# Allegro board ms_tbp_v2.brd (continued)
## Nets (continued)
SAS_B2_TX4P: J23.G3 J24.1C7
SAS_B2_TX5N: J23.F4 J24.2D5
SAS_B2_TX5P: J23.E4 J24.2D4
SAS_B2_TX6N: J23.B5 J24.2C5
SAS_B2_TX6P: J23.A5 J24.2C4
SAS_B2_TX7N: J23.H5 J24.2D8
SAS_B2_TX7P: J23.G5 J24.2D7
SAS_B2_TX8N: J23.F6 J24.2C8
SAS_B2_TX8P: J23.E6 J24.2C7
SERIAL_B1_RX1: J7.G3 J11.B3 U1.S2
SERIAL_B1_RX2: J1.I8 J7.G4 U1.S6
SERIAL_B1_TX1: J7.H3 J11.A3 U1.S1
SERIAL_B1_TX2: J1.H8 J7.H4 U1.S5
SERIAL_B2_RX1: J19.G3 J23.B3 U1.S11
SERIAL_B2_RX2: J13.I8 J19.G4 U1.S7
SERIAL_B2_TX1: J19.H3 J23.A3 U1.S12
SERIAL_B2_TX2: J13.H8 J19.H4 U1.S8
SKU_B1_ID0: J7.F3 R2.2(B<0>) R3.1(A<0>)
SKU_B1_ID1: J7.I4 R4.2(B<0>) R5.1(A<0>)
SKU_B1_ID2: J7.F2 R6.2(B<0>) R7.1(A<0>) R75.1(A<0>)
SKU_B2_ID0: J19.F3 R30.2(B<0>) R31.1(A<0>)
SKU_B2_ID1: J19.I4 R32.2(B<0>) R33.1(A<0>)
SKU_B2_ID2: J19.F2 R34.2(B<0>) R35.1(A<0>) R61.1(A<0>)
UNNAMED_4_1X2HDR_I81_IO: J25.2(IO<2>) R9.1(A<0>)
UNNAMED_4_1X2HDR_I90_IO: J26.2(IO<2>) R11.1(A<0>)
UNNAMED_4_FERRITE_I148_A: FB1.1(A) FS1.2(B<0>)
UNNAMED_4_FERRITE_I151_B: FB2.2(B) FS2.1(A<0>)
UNNAMED_6_1X2HDR_I52_IO: J28.2(IO<2>) R37.1(A<0>)
UNNAMED_6_1X2HDR_I56_IO: J29.2(IO<2>) R39.1(A<0>)
UNNAMED_6_FERRITE_I24_A: FB3.1(A) FS3.2(B<0>)
UNNAMED_6_FERRITE_I27_B: FB4.2(B) FS4.1(A<0>)
UNNAMED_8_FERRITE_I47_B: FB7.2(B) FS7.1(A<0>)
UNNAMED_8_FERRITE_I51_A: FB5.1(A) FS5.2(B<0>)
UNNAMED_8_FERRITE_I54_A: FB6.1(A) FS6.2(B<0>)
UNNAMED_16_FERRITE_I40_A: FB9.1(A) FS9.2(B<0>)
UNNAMED_16_FERRITE_I46_B: FB10.2(B) FS10.1(A<0>)
UNNAMED_16_FERRITE_I115_A: FB8.1(A) FS8.2(B<0>)
USB_B1_N: J1.C10 U2.2(IO<2>)
USB_B1_P: J1.B10 U2.3(IO<3>)
USB_B2_N: J13.C10 U3.2(IO<2>)
USB_B2_P: J13.B10 U3.3(IO<3>)

Pads without a net: J1 G7; J7 E2; J12 1A1 1A2 1B1 1B2 1C1 1C2 1D1 1D2 2A1 2A2 2B1 2B2 2C1 2C2 2D1 2D2; J13 G7; J19 E2; J24 1A1 1A2 1B1 1B2 1C1 1C2 1D1 1D2 2A1 2A2 2B1 2B2 2C1 2C2 2D1 2D2

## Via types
v1: diameter 0.559, hole 0.254, TOP to BOTTOM, 1600 vias

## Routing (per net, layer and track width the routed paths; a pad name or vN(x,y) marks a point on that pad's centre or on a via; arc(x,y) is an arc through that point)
GND: length 293.7
  TOP w0.305: J14.135 v1(270.92,27.93) ; J8.20 v1(99.21,4.79) ; v1(359.71,15.27) J17.14 v1(359.71,12.39) ; J2.79 v1(49.92,19.04) ; J2.118 v1(48.65,25.39) ; J2.22 v1(48.65,10.15) ; R11.2 77.91,43.55 v1(77.86,43.5) ; C8.2 v1(136.74,5.51) ; C7.2 v1(136.74,6.65) ; J14.120 v1(272.19,25.39) ; J2.58 v1(43.57,16.5) ; J14.58 v1(264.57,16.5) ; J2.147 v1(44.84,30.47) ; J2.126 v1(48.65,26.66) ; J14.141 v1(268.38,29.2) ; J14.105 v1(263.21,23.49) ; J2.11 v1(44.84,8.88) ; R12.2 v1(122.99,39.71) ; J2.77 v1(47.38,19.04) ; J20.38 v1(334.61,4.79) ; C12.2 v1(357.74,5.51) ; J2.13 v1(47.38,8.88) ; v1(43.58,11.43) 43.57,11.43 43.57,11.42 J2.26 ; v1(263.21,22.22) 263.43,22.22 263.45,22.19 263.89,22.19 263.92,22.22 J14.97 ; J2.141 v1(47.38,29.2) ; J14.124 v1(267.11,26.66) ; J20.23 v1(322.61,4.79) ; v1(138.71,12.39) J5.14 v1(138.71,15.27) ; J8.4 110.81,10.06 v1(110.81,10.03) ; J2.56 v1(51.19,15.23) ; J14.35 v1(265.84,12.69) ; J14.101 v1(268.38,22.85) ; R23.2 v1(124.9,44.48) ; v1(85.95,29.14) 85.97,29.16 C4.2 ; C1.2 88.95,29.48 v1(88.95,29.47) ; J14.56 v1(272.19,15.23) ; v1(357.31,15.27) J17.11 v1(357.31,12.41) ; J2.135 v1(49.92,27.93) ; v1(42.21,22.22) 42.43,22.22 42.45,22.19 42.89,22.19 42.92,22.22 J2.97 ; J14.65 262.95,17.14 v1(262.77,16.95) ; J2.107 v1(44.84,24.12) ; J2.32 v1(51.19,11.42) ; v1(263.23,14.11) 263.94,13.4 J14.41 ; v1(310.19,42.51) 310.2,42.51 R63.2 ; J14.52 v1(267.11,15.23) ; J14.88 v1(272.19,20.31) ; J20.1 334.21,10.06 v1(334.21,10.03) ; J2.129 v1(42.21,27.3) ; J14.24 v1(272.19,10.15) ; J2.146 v1(43.57,30.47) ; v1(403.43,6.44) 403.41,6.45 R71.1 ; C5.2 v1(144.01,6.65) ; J2.96 v1(51.19,21.58) ; R86.1 258.95,18.16 v1(258.96,18.15) ; J2.62 v1(48.65,16.5) ; J14.9 v1(263.21,8.25) ; J2.65 v1(42.21,17.14) ; J14.147 v1(265.84,30.47) ; v1(356.74,23.54) 356.91,23.37 J17.10 ; v1(263.15,11.57) 263.64,12.05 J14.33 ; J5.1 143.11,23.34 v1(143.31,23.54) ; R39.2 v1(298.91,43.36) ; J14.67 v1(265.84,17.77) ; J2.64 v1(51.19,16.5) ; J14.3 v1(265.84,7.61) ; J2.35 v1(44.84,12.69) ; J20.26 v1(325.01,4.79) ; J2.124 v1(46.11,26.66) ; C3.2 v1(70.09,16.17) ; v1(136.31,12.41) J5.11 v1(136.31,15.27) ; J2.101 v1(47.38,22.85) ; J14.107 v1(265.84,24.12) ; v1(362.11,12.39) J17.17 v1(362.11,15.27) ; J2.88 v1(51.19,20.31) ; J2.71 v1(49.92,17.77) ; J2.75 v1(44.84,19.04) ; R79.2 v1(92.56,42.33) ; J8.1 113.21,10.06 v1(113.21,10.03) ; J14.114 v1(264.57,25.39) ; J14.126 v1(269.65,26.66) ; J2.92 v1(46.11,21.58) ; v1(143.51,12.39) J5.20 v1(143.51,15.27) ; v1(364.51,12.39) J17.20 v1(364.51,15.27) ; J2.41 v1(42.21,13.33) ; J14.1 v1(263.21,6.98) ; J14.122 v1(264.57,26.66) ; J14.54 v1(269.65,15.23) ; J20.7 329.41,10.06 v1(329.41,10.03) ; v1(144.03,5.51) C6.2 ; v1(309.57,29.5) 309.57,29.5 C13.2 ; J20.16 322.21,10.06 v1(322.21,10.03) ; R25.2 v1(119.95,45.36) ; v1(141.11,15.27) J5.17 v1(141.11,12.39) ; J14.39 v1(270.92,12.69) ; J14.84 v1(267.11,20.31) ; J14.22 v1(269.65,10.15) ; J20.13 324.61,10.06 v1(324.61,10.03) ; J2.24 v1(51.19,10.15) ; J2.114 v1(43.57,25.39) ; J14.43 v1(265.84,13.96) ; J2.37 v1(47.38,12.69) ; J14.28 v1(267.11,11.42) ; J14.103 v1(270.92,22.85) ; v1(364.31,23.54) 364.11,23.34 J17.1 ; J2.82 v1(43.57,20.31) ; J2.94 v1(48.65,21.58) ; J2.28 v1(46.11,11.42) ; R21.2 v1(124.77,47.27) ; J14.92 v1(267.11,21.58) ; J8.35 v1(111.21,4.79) ; R37.2 v1(307.04,43.15) ; J14.30 v1(269.65,11.42) ; J14.11 v1(265.84,8.88) ; v1(319.81,10.03) 319.81,10.06 J20.19 ; J2.45 v1(47.38,13.96) ; J2.90 v1(43.57,21.58) ; J8.32 v1(108.81,4.79) ; J2.9 v1(42.21,8.25) ; J14.5 v1(268.38,7.61) ; J20.4 331.81,10.06 v1(331.81,10.03) ; J2.111 v1(49.92,24.12) ; v1(89.57,38.14) 89.57,38.14 R77.2 ; C11.2 v1(357.74,6.65) ; J14.133 v1(268.38,27.93) ; J2.60 v1(46.11,16.5) ; J8.19 98.81,10.06 v1(98.81,10.03) ; J14.20 v1(267.11,10.15) ; J14.86 v1(269.65,20.31) ; R9.2 v1(86.04,43.15) ; J14.32 v1(272.19,11.42) ; J2.116 v1(46.11,25.39) ; J14.73 v1(264.57,19.04) ; J8.23 v1(101.61,4.79) ; J2.7 v1(49.92,7.61) ; J2.39 v1(49.92,12.69) ; J14.146 v1(264.57,30.47) ; J14.109 v1(268.38,24.12) ; J14.18 v1(264.57,10.15) ; J2.3 v1(44.84,7.61) ; J2.47 v1(49.92,13.96) ; J14.82 v1(264.57,20.31) ; J14.26 264.57,11.42 264.57,11.43 v1(264.58,11.43) ; J2.122 v1(43.57,26.66) ; J2.20 v1(46.11,10.15) ; J2.99 v1(44.84,22.85) ; J2.133 v1(47.38,27.93) ; J14.45 v1(268.38,13.96) ; J8.38 v1(113.61,4.79) ; J14.13 v1(268.38,8.88) ; J2.15 v1(49.92,8.88) ; J5.10 135.91,23.37 v1(135.74,23.54) ; J20.32 v1(329.81,4.79) ; J2.86 v1(48.65,20.31) ; J8.13 103.61,10.06 v1(103.61,10.03) ; J2.67 v1(44.84,17.77) ; J2.18 v1(43.57,10.15) ; J14.139 v1(265.84,29.2) ; J2.50 v1(43.57,15.23) ; J8.16 101.21,10.06 v1(101.21,10.03) ; J14.62 v1(269.65,16.5) ; J14.75 v1(265.84,19.04) ; J14.37 v1(268.38,12.69) ; J2.52 v1(46.11,15.23) ; J2.131 v1(44.84,27.93) ; J2.1 v1(42.21,6.98) ; J14.69 v1(268.38,17.77) ; J14.118 v1(269.65,25.39) ; C15.2 306.59,29.18 v1(306.58,29.17) ; J14.116 v1(267.11,25.39) ; J14.131 v1(265.84,27.93) ; J2.54 v1(48.65,15.23) ; J14.90 v1(264.57,21.58) ; J14.129 v1(263.21,27.3) ; J14.94 v1(269.65,21.58) ; J14.111 v1(270.92,24.12) ; J2.73 v1(42.21,18.41) ; J8.26 v1(104.01,4.79) ; J2.30 v1(48.65,11.42) ; R5.2 120.05,41.14 v1(119.82,41.36) ; R3.2 v1(127.82,40.22) ; J2.139 v1(44.84,29.2) ; J14.99 v1(265.84,22.85) ; J2.103 v1(49.92,22.85) ; J14.79 v1(270.92,19.04) ; J2.105 v1(42.21,23.49) ; J8.7 108.41,10.06 v1(108.41,10.03) ; R85.1 v1(35.27,18.16) ; J2.84 v1(46.11,20.31) ; J2.69 v1(47.38,17.77) ; J14.71 v1(270.92,17.77) ; J2.120 v1(51.19,25.39) ; J14.96 v1(272.19,21.58) ; J14.60 v1(267.11,16.5) ; J14.64 v1(272.19,16.5) ; J14.50 v1(264.57,15.23) ; J14.128 v1(272.19,26.66) ; C9.2 v1(365.01,6.65) ; v1(365.03,5.51) C10.2 ; C2.2 v1(66.83,16.59) ; J20.35 v1(332.21,4.79) ; J14.47 v1(270.92,13.96) ; J2.128 v1(51.19,26.66) ; J14.77 v1(268.38,19.04) ; J14.7 v1(270.92,7.61) ; J2.5 v1(47.38,7.61) ; J14.15 v1(270.92,8.88) ; J2.33 v1(42.21,12.05) ; J20.20 v1(320.21,4.79) ; J2.109 v1(47.38,24.12) ; J2.43 v1(44.84,13.96)
  TOP w0.381: 216.52,25.69 J27.4 ; J27.4 218.52,25.69 ; J27.4 218.52,23.7 ; J27.4 216.52,23.7 ; 220.08,14.12 U3.4 ; U3.4 221.63,14.12 ; U3.4 221.63,15.66 ; U3.4 220.08,15.66 ; J27.2 224.02,25.69 ; J27.2 224.02,23.7 ; J27.2 222.02,25.69 ; J27.2 222.02,23.7
  LYR2 w0.381: 216.52,25.69 J27.4 ; J27.4 218.52,23.7 ; J27.4 218.52,25.69 ; J27.4 216.52,23.7 ; J27.2 224.02,23.7 ; J27.2 222.02,23.7 ; J27.2 222.02,25.69 ; J27.2 224.02,25.69 ; 2.84,25.91 U2.4 ; U2.4 2.84,24.37 ; U2.4 4.39,24.37 ; U2.4 4.39,25.91 ; 220.08,14.12 U3.4 ; U3.4 221.63,15.66 ; U3.4 220.08,15.66 ; U3.4 221.63,14.12
  LYR3 w0.381: 222.02,25.69 J27.2 ; J27.2 224.02,25.69 ; J27.2 224.02,23.7 ; J27.2 222.02,23.7 ; J27.4 218.52,25.69 ; J27.4 218.52,23.7 ; J27.4 216.52,25.69 ; J27.4 216.52,23.7 ; 220.08,14.12 U3.4 ; U3.4 220.08,15.66 ; U3.4 221.63,15.66 ; U3.4 221.63,14.12
  LYR5 w0.381: 2.84,25.91 U2.4 ; U2.4 2.84,24.37 ; U2.4 4.39,24.37 ; U2.4 4.39,25.91
  LYR7 w0.381: J27.2 224.02,23.7 ; J27.2 224.02,25.69 ; J27.2 222.02,23.7 ; J27.2 222.02,25.69 ; U3.4 221.63,15.66 ; U3.4 220.08,14.12 ; U3.4 220.08,15.66 ; U3.4 221.63,14.12 ; 216.52,25.69 J27.4 ; J27.4 218.52,23.7 ; J27.4 218.52,25.69 ; J27.4 216.52,23.7 ; 2.84,25.91 U2.4 ; U2.4 4.39,24.37 ; U2.4 2.84,24.37 ; U2.4 4.39,25.91
  vias: v1(1.2,42.13) v1(1.84,15.71) v1(7.68,15.58) v1(32.55,46.91) v1(32.55,45.64) v1(32.55,44.37) v1(33.82,46.91) v1(33.82,45.64) v1(33.82,44.37) v1(35.09,46.91) v1(35.09,45.64) v1(35.09,44.37) v1(36.36,46.91) v1(36.36,45.64) v1(36.36,44.37) v1(37.63,46.91) v1(37.63,45.64) v1(37.63,44.37) v1(38.9,46.91) v1(38.9,45.64) v1(38.9,44.37) v1(40.17,46.91) v1(40.17,45.64) v1(40.17,44.37) v1(41.44,46.91) v1(41.44,45.64) v1(41.44,44.37) v1(42.71,46.91) v1(42.71,45.64) v1(42.71,44.37) v1(43.98,46.91) v1(43.98,45.64) v1(43.98,44.37) v1(45.25,46.91) v1(45.25,45.64) v1(45.25,44.37) v1(46.52,46.91) v1(46.52,45.64) v1(46.52,44.37) v1(47.79,46.91) v1(47.79,45.64) v1(47.79,44.37) v1(49.06,46.91) v1(49.06,45.64) v1(49.06,44.37) v1(50.33,46.91) v1(50.33,45.64) v1(50.33,44.37) v1(54.16,27.77) v1(54.16,21.42) v1(54.16,15.07) v1(54.16,8.72) v1(57.34,24.6) v1(57.34,5.55) v1(57.59,27.77) v1(57.97,50.25) v1(58.86,29.43) v1(59.11,26.25) v1(59.24,30.85) v1(60.51,8.72) v1(61.46,29.36) v1(61.78,53.68) v1(61.91,45.43) v1(62.16,26.25) v1(63.69,34.12) v1(63.69,5.55) v1(63.81,24.47) v1(65.27,29.04) v1(65.27,23.01) v1(66.73,25.49) v1(66.86,30.95) v1(66.86,21.42) v1(66.86,8.72) v1(68,53.57) v1(68.13,49.87) v1(68.13,23.01) v1(68.26,45.43) v1(68.45,29.04) v1(70.04,34.12) v1(70.04,18.25) v1(70.04,11.9) v1(70.04,5.55) v1(71.31,51.78) v1(71.31,47.97) v1(71.62,29.04) v1(71.94,23.01) v1(73.21,30.95) v1(73.51,36.56) v1(74.16,21.42) v1(74.48,53.68) v1(74.48,49.87) v1(74.8,29.04) v1(76.07,23.01) v1(76.39,34.12) v1(77.66,51.78) v1(77.66,47.97) v1(77.97,29.04) v1(79.41,30.95) v1(80.83,53.68) v1(80.83,49.87) v1(81.29,28.99) v1(82.74,34.12) v1(84.01,51.78) v1(84.01,43.01) v1(84.54,30.98) v1(87.18,53.68) v1(87.18,49.87) v1(90.36,51.78) v1(93.53,53.68) v1(99.02,12.03) v1(99.02,10.86) v1(99.42,3.94) v1(99.42,2.77) v1(99.88,53.68) v1(101,12.03) v1(101,10.86) v1(101.39,13.94) v1(101.34,4.01) v1(101.4,2.77) v1(101.42,12.73) v1(103.06,35.39) v1(103.4,13.9) v1(103.4,12.73) v1(105.47,3.16) v1(105.47,1.18) v1(106.23,53.68) v1(106.23,44.92) v1(106.23,38.57) v1(106.23,32.22) v1(106.63,3.16) v1(106.63,1.18) v1(108.05,3.5) v1(108.05,2.33) v1(108.62,16.46) v1(108.62,15.29) v1(109.41,38.57) v1(109.41,35.39) v1(110.03,3.5) v1(110.03,2.33) v1(110.6,16.46) v1(110.6,15.29) v1(111.03,12.51) v1(111.03,11.34) v1(112.58,53.68) v1(113.01,12.51) v1(113.01,11.34) v1(114.68,8.07) v1(114.68,6.91) v1(116.66,8.07) v1(116.66,6.91) v1(117.79,51.37) v1(118.93,53.68) v1(125.28,53.68) v1(131.63,53.68) v1(133.54,49.36) v1(136.46,46.19) v1(136.52,11.17) v1(136.52,10) v1(136.76,17.23) v1(137.88,17.23) v1(137.98,53.68) v1(138.5,11.17) v1(138.5,10) v1(140.14,49.36) v1(140.27,20.5) v1(140.27,18.51) v1(141.43,20.5) v1(141.43,18.51) v1(143.06,46.19) v1(144.33,53.68) v1(160.21,53.68) v1(164.46,24.46) v1(164.6,31.18) v1(165.19,39.52) v1(165.29,48.09) v1(165.25,35.76) v1(165.25,32) v1(165.25,28.18) v1(166.25,30.7) v1(166.32,26.78) v1(166.56,53.68) v1(167.5,35.76) v1(167.6,27.91) v1(168.5,34.54) v1(168.5,30.73) v1(168.47,26.96) v1(169.31,30.83) v1(169.91,39.61) v1(172.78,48.09) v1(172.91,53.68) v1(175.63,31.25) v1(176.25,28.18) v1(176.25,24.38) v1(177.25,38.34) v1(177.25,30.73) v1(177.22,26.96) v1(178.55,24.33) v1(179.18,35.34) v1(179.26,53.68) v1(179.26,48.09) v1(179.5,38.34) v1(179.5,34.54) v1(179.5,30.73) v1(179.47,26.96) v1(180.33,30.86) v1(185.61,53.68) v1(185.61,48.09) v1(188.15,51.27) v1(188.15,44.92) v1(188.15,38.57) v1(188.15,32.22) v1(188.15,25.87) v1(188.15,19.52) v1(188.15,6.82) v1(191.32,48.09) v1(191.32,35.39) v1(191.32,29.04) v1(191.32,22.69) v1(191.32,16.34) v1(191.32,9.49) v1(191.45,53.68) v1(194.5,51.27) v1(194.5,44.92) v1(194.5,38.57) v1(194.5,32.22) v1(194.5,25.87) v1(194.5,6.82) v1(197.67,53.68) v1(197.67,48.09) v1(197.67,35.39) v1(197.67,29.04) v1(197.67,22.69) v1(197.67,16.34) v1(197.67,9.49) v1(200.85,51.27) v1(200.85,44.92) v1(200.85,38.57) v1(200.85,32.22) v1(200.85,25.87) v1(200.85,6.82) v1(204.02,53.68) v1(204.02,48.09) v1(204.02,35.39) v1(204.02,29.04) v1(204.02,22.69) v1(204.02,16.34) v1(204.02,9.49) v1(207.2,51.27) v1(207.2,44.92) v1(207.2,38.57) v1(207.2,32.22) v1(207.2,25.87) v1(207.2,6.82) v1(210.24,53.68) v1(210.37,35.39) v1(210.37,29.04) v1(210.37,22.69) v1(210.37,16.34) v1(210.37,9.49) v1(213.55,51.27) v1(213.55,44.92) v1(213.55,38.57) v1(213.55,32.22) v1(213.55,25.87) v1(213.55,19.52) v1(213.55,13.17) v1(213.55,6.82) v1(216.72,53.68) v1(216.72,48.09) v1(216.72,38.57) v1(216.72,35.39) v1(216.72,32.22) v1(216.72,19.52) v1(216.72,16.34) v1(216.72,13.17) v1(216.72,9.99) v1(216.72,6.82) v1(219.9,51.27) v1(219.9,44.92) v1(219.9,38.57) v1(219.9,35.39) v1(219.9,32.22) v1(219.9,19.52) v1(222.94,19.52) v1(223.07,53.68) v1(223.07,48.09) v1(223.07,38.57) v1(223.07,35.39) v1(223.07,32.22) v1(226.25,51.27) v1(226.25,44.92) v1(226.25,38.57) v1(226.25,32.22) v1(226.25,25.87) v1(226.25,19.52) v1(226.25,13.17) v1(226.25,6.82) v1(229.42,53.68) v1(229.42,48.09) v1(229.42,35.39) v1(229.42,29.04) v1(229.42,22.69) v1(229.42,16.34) v1(232.6,51.27) v1(232.6,44.92) v1(232.6,38.57) v1(235.77,53.68) v1(235.77,48.09) v1(235.77,35.39) v1(238.95,51.27) v1(238.95,44.92) v1(238.95,38.57) v1(242.12,53.68) v1(242.12,48.09) v1(245.3,51.27) v1(245.3,44.92) v1(245.3,38.57) v1(248.47,53.68) v1(248.47,48.09) v1(251.65,51.27) v1(251.65,44.92) v1(251.65,38.57) v1(254.82,53.68) v1(255.96,49.87) v1(255.96,46.82) v1(255.96,40.47) v1(261.81,53.68) v1(262.44,46.82) v1(262.44,43.52) v1(266,53.68) v1(266,46.82) v1(266,40.47) v1(269.43,53.17) v1(269.43,46.82) v1(269.43,40.47) v1(272.6,50) v1(272.6,43.65) v1(275.78,53.17) v1(275.78,46.82) v1(275.78,40.47) v1(275.78,17.61) v1(275.78,11.26) v1(275.78,4.91) v1(278.95,50) v1(278.95,43.65) v1(278.95,33.49) v1(278.95,14.44) v1(278.95,8.09) v1(282.13,53.17) v1(282.13,46.82) v1(282.13,40.47) v1(282.13,11.26) v1(282.13,4.91) v1(285.3,50) v1(285.3,43.65) v1(285.3,33.49) v1(285.3,27.14) v1(285.3,20.79) v1(285.3,14.44) v1(285.3,8.09) v1(288.48,53.17) v1(288.48,46.82) v1(288.48,40.47) v1(288.48,30.31) v1(288.48,23.96) v1(288.48,17.61) v1(288.48,11.26) v1(288.48,4.91) v1(291.65,50) v1(291.65,43.65) v1(291.65,33.49) v1(291.65,27.14) v1(291.65,20.79) v1(291.65,14.44) v1(291.65,8.09) v1(294.83,53.17) v1(294.83,46.82) v1(294.83,40.47) v1(294.83,30.31) v1(294.83,23.96) v1(298,50) v1(298,27.14) v1(301.18,53.17) v1(301.18,40.47) v1(304.35,43.65) v1(305.25,51.67) v1(307.53,53.17) v1(309.7,51.67) v1(313.88,53.17) v1(317.43,53.17) v1(320.02,12.03) v1(320.02,10.86) v1(320.23,53.17) v1(320.42,3.94) v1(320.42,2.77) v1(322,12.03) v1(322,10.86) v1(322.39,13.94) v1(322.34,4.01) v1(322.4,2.77) v1(322.42,12.73) v1(323.4,53.17) v1(324.29,48.6) v1(324.29,45.17) v1(324.29,42) v1(324.29,38.82) v1(324.29,35.65) v1(324.4,13.9) v1(324.4,12.73) v1(326.47,3.16) v1(326.47,1.18) v1(326.58,53.17) v1(327.46,45.17) v1(327.46,42) v1(327.46,38.82) v1(327.46,35.65) v1(327.63,3.16) v1(327.63,1.18) v1(329.05,3.5) v1(329.05,2.33) v1(329.62,16.46) v1(329.62,15.29) v1(329.75,53.17) v1(330.64,45.17) v1(330.64,42) v1(330.64,38.82) v1(330.64,35.65) v1(330.89,27.88) v1(331.03,3.5) v1(331.03,2.33) v1(331.6,16.46) v1(331.6,15.29) v1(332.03,12.51) v1(332.03,11.34) v1(332.62,27.75) v1(332.93,53.17) v1(334.07,45.17) v1(334.07,42) v1(334.07,38.82) v1(334.07,35.52) v1(334.11,27.89) v1(334.01,12.51) v1(334.01,11.34) v1(335.49,27.77) v1(335.68,8.07) v1(335.68,6.91) v1(336.1,53.17) v1(337.12,46.06) v1(337.12,42.89) v1(337.12,36.54) v1(337.66,8.07) v1(337.66,6.91) v1(339.28,53.17) v1(340.29,33.36) v1(342.45,53.17) v1(345.63,53.17) v1(348.8,53.17) v1(350.07,23.81) v1(350.07,22.72) v1(351.98,53.17) v1(354.39,49.87) v1(354.39,46.7) v1(355.15,53.17) v1(357.56,49.87) v1(357.56,46.7) v1(357.56,43.52) v1(357.52,11.17) v1(357.52,10) v1(357.76,17.23) v1(358.33,53.17) v1(358.88,17.23) v1(359.5,11.17) v1(359.5,10) v1(360.74,49.87) v1(360.74,46.7) v1(360.74,43.52) v1(360.74,39.71) v1(361.27,20.5) v1(361.27,18.51) v1(361.5,53.17) v1(362.43,20.5) v1(362.43,18.51) v1(363.91,49.87) v1(364.04,46.57) v1(364.68,53.17) v1(367.85,53.17) v1(371.03,53.17) v1(374.1,53.24) v1(377.38,53.17) v1(380.55,53.17) v1(383.73,53.17) v1(385.46,24.46) v1(385.6,31.18) v1(386.25,35.76) v1(386.25,32) v1(386.25,28.18) v1(386.36,39.51) v1(386.9,53.17) v1(387.15,47.84) v1(387.15,44.67) v1(387.25,30.7) v1(387.3,26.79) v1(388.5,35.76) v1(388.6,27.91) v1(389.5,34.54) v1(389.5,30.7) v1(389.47,26.96) v1(390.08,53.17) v1(390.3,30.85) v1(390.33,47.84) v1(390.33,44.67) v1(390.81,39.46) v1(393.25,53.17) v1(393.5,47.84) v1(393.5,44.67) v1(393.5,41.49) v1(396.43,53.17) v1(396.68,47.84) v1(396.68,44.67) v1(396.68,41.49) v1(396.63,31.25) v1(397.25,28.18) v1(397.25,24.38) v1(398.25,38.34) v1(398.25,30.73) v1(398.22,26.96) v1(399.6,53.17) v1(399.55,24.33) v1(399.85,47.84) v1(399.85,44.67) v1(400.18,35.34) v1(400.5,38.34) v1(400.5,34.54) v1(400.5,30.73) v1(400.47,26.96) v1(401.3,30.86) v1(402.78,53.17) v1(403.03,47.84) v1(403.03,44.67) v1(403.03,41.49) v1(404.25,19.27) v1(404.3,16.09) v1(404.3,12.92) v1(404.3,9.74) v1(404.55,22.42) v1(405.95,53.17) v1(407.35,47.84) v1(407.35,44.67) v1(407.35,41.49) v1(407.35,38.32) v1(407.35,35.14) v1(407.35,31.97) v1(407.35,28.79) v1(407.35,25.62) v1(407.35,22.44) v1(407.35,18.63) v1(407.35,15.46) v1(407.35,12.28) v1(407.35,9.11) v1(407.35,5.93) v1(408.62,50.38) v1(409.13,53.17) v1(410.52,47.84) v1(410.52,44.67) v1(410.52,41.49) v1(410.52,38.32) v1(410.52,35.14) v1(410.52,31.97) v1(410.52,28.79) v1(411.54,12.92) v1(411.54,9.74) v1(411.67,5.93) v1(411.79,50.38) v1(412.3,53.17) v1(413.7,47.84) v1(413.7,44.67) v1(413.7,41.49) v1(413.7,38.32) v1(413.7,35.14) v1(413.7,31.97) v1(413.7,28.79) v1(414.71,12.92) v1(414.71,9.74) v1(415.48,53.17) v1(416.87,47.84) v1(416.87,44.67) v1(416.87,41.49) v1(416.87,38.32) v1(416.87,35.14) v1(416.87,31.97) v1(417.09,28.77) v1(417.89,12.92) v1(417.89,9.74) v1(417.89,5.93) v1(418.14,50.38) v1(418.65,53.17) v1(420.05,47.84) v1(420.05,44.67) v1(420.05,41.49) v1(420.05,38.32) v1(420.05,35.14) v1(420.05,31.97) v1(420.09,28.79) v1(420.05,25.62) v1(420.05,22.44) v1(420.05,19.52) v1(421.83,53.17) v1(423.22,47.84) v1(423.22,44.67) v1(423.22,41.49) v1(423.22,38.32) v1(423.22,35.14) v1(423.22,31.97) v1(423.22,28.79) v1(423.22,25.62) v1(423.22,22.44) v1(423.22,19.52)
P3V3_10G_B1_VCCR: length 17.8
  LYR6 w0.508: v1(139.38,17.23) 138.42,16.28 136.09,16.28 135.22,15.41 135.22,14 133.56,12.34 133.56,10.9 136.34,8.12 138.21,8.12 139.26,7.07 v1(139.26,6.64)
P3V3_10G_B1_VCCT: length 16.8
  LYR6 w0.508: v1(140.39,17.23) 141.48,16.14 144.01,16.14 145.91,14.24 145.91,11.17 144.64,9.9 143.79,9.9 141.29,7.4 v1(141.29,6.64)
P3V3_10G_B2_VCCR: length 17.8
  LYR6 w0.508: v1(360.26,6.64) 360.26,7.07 359.21,8.12 357.34,8.12 354.56,10.9 354.56,12.34 356.22,14 356.22,15.41 357.09,16.28 359.53,16.28 v1(360.41,17.16)
P3V3_10G_B2_VCCT: length 16.7
  LYR6 w0.508: v1(362.29,6.64) 362.29,7.4 364.79,9.9 365.64,9.9 366.91,11.17 366.91,14.24 365.01,16.14 362.44,16.14 v1(361.42,17.16)
P3V3_40G_B1_VCC1: length 67.9
  TOP w0.305: J8.30 v1(107.21,4.53)
  LYR3 w0.508: v1(152.31,35.62) 148.04,31.36 v1(141.1,31.36)
  LYR6 w0.508: v1(107.21,4.53) 107.24,4.56 107.24,5.03 107.58,5.37 107.58,17.15 113.35,22.92 116.47,22.92 117.84,21.55 125.94,21.55 135.74,31.36 v1(141.1,31.36)
  vias: v1(154.01,35.7)
P3V3_40G_B1_VCC_RX: length 73
  LYR3 w0.508: v1(152.74,48.68) 151.75,48.68 148.88,45.81 148.88,37.78 145.07,33.97 v1(141.1,33.97)
  LYR6 w0.508: v1(141.1,33.97) 135.01,33.97 124.31,23.28 120.58,23.28 118.4,25.46 113.47,25.46 105.93,17.92 105.93,11.06 v1(105.88,11.01)
  vias: v1(154.59,48.7)
P3V3_40G_B1_VCC_TX: length 75.3
  TOP w0.305: J8.29 v1(106.41,4.79)
  LYR3 w0.508: v1(152.71,42.58) 151.67,42.58 150.58,41.49 150.58,36.51 146.74,32.68 v1(141.08,32.68)
  LYR6 w0.508: v1(106.41,4.79) 106.41,6.14 106.74,6.46 106.74,17.49 113.85,24.6 117.58,24.6 119.74,22.44 125.18,22.44 135.41,32.68 v1(141.08,32.68)
  vias: v1(154.52,42.43)
P3V3_40G_B2_VCC1: length 67.7
  TOP w0.305: J20.30 v1(328.21,4.53)
  LYR4 w0.508: v1(328.21,4.53) 328.21,5.99 328.63,6.42 328.63,10.79 331.28,13.43 332.83,13.43 338.41,19.01 353.78,19.01 355.48,20.71 355.48,23.94 359.52,27.98 359.52,29.35 361.68,31.51 364.4,31.51 368.57,35.67 v1(373.95,35.67) 375.19,35.67 v1(375.24,35.73)
P3V3_40G_B2_VCC_RX: length 70.1
  TOP w0.305: J20.10 327.01,10.88 v1(327.01,10.88)
  LYR4 w0.508: v1(375.93,48.83) 375.83,48.93 v1(374.12,48.93) 371.73,46.54 369.3,46.54 356.12,33.35 356.12,32.65 355.07,31.61 353.96,31.61 348.17,25.82 348.17,25.11 346.31,23.25 335.33,23.25 327.01,14.93 v1(327.01,10.88)
P3V3_40G_B2_VCC_TX: length 69.4
  TOP w0.305: J20.29 v1(327.41,4.79)
  LYR4 w0.508: v1(376,42.43) 375.77,42.66 v1(374.12,42.66) 368.78,42.66 362.12,36 361.53,36 355.84,30.31 355.07,30.31 346.92,22.16 340.04,22.16 332.11,14.24 330.61,14.24 327.82,11.45 327.82,8.12 327.41,7.71 v1(327.41,4.79)
P3V3_B1_QSFP: length 25.3
  TOP w0.305: FS1.1 135.09,4.32 v1(134.28,4.32)
  TOP w0.381: R81.1 v1(89.58,33.95) ; v1(124.75,48.63) 124.76,48.62 R18.1 ; v1(146.97,4.32) 146.93,4.36 FS2.2 ; v1(157.21,37.89) 157.19,37.91 FS10.2 ; R4.1 119.74,42.53 v1(119.72,42.51) ; R13.1 v1(139.67,3.72) ; R17.2 v1(141.07,3.7) ; R26.1 R28.1 127.87,38.82 v1(127.9,38.85) ; R76.1 v1(89.58,36.74) ; R72.1 156.92,40.36 v1(156.93,40.35) ; R82.1 v1(89.58,35.34) ; R29.2 v1(119.82,50) ; R27.1 v1(119.9,46.92) ; v1(157,36.56) 156.99,36.58 R74.2 ; R24.1 v1(120,44.04) ; R2.1 127.85,41.62 v1(127.87,41.59) ; R83.1 v1(89.58,39.54) ; R78.1 v1(89.58,40.93) ; FS8.1 155.53,43.52 v1(155.4,43.4) ; R73.1 157.94,47.46 v1(157.97,47.43) ; v1(157.97,45.81) 157.94,45.78 C39.1 ; R84.1 v1(87.76,31.53) ; FS9.1 v1(155.55,50.66) ; R20.1 v1(124.82,45.87) ; R22.1 v1(124.82,43.15) ; R6.1 v1(89.58,31.15)
  vias: v1(143.21,27.09) v1(144.74,27.09) v1(149.92,27.06)
P3V3_B2_QSFP: length 24.9
  TOP w0.305: FS5.1 376.79,43.83 v1(376.79,44.59) ; R57.2 v1(340.71,49.62) ; R59.1 v1(379.15,47.46) ; FS7.2 378.28,38.02 v1(378.31,37.99) ; FS6.1 377.04,51.09 v1(376.99,51.14) ; R60.2 378.45,36.7 v1(378.47,36.69) ; C27.1 v1(379.2,45.81) ; FS3.1 355.14,4.28 v1(355.1,4.32) ; R58.1 v1(379.23,41.24) ; v1(367.98,4.33) 367.95,4.31 FS4.2
  TOP w0.381: v1(345.52,40.37) 345.55,40.35 R50.1 ; R67.1 v1(310.2,33.97) ; R52.1 v1(348.62,47.52) ; R70.1 v1(308.39,34.55) ; R64.1 v1(310.2,36.77) ; R46.1 v1(345.68,48.87) ; v1(340.57,42.13) 340.6,42.15 R32.1 ; R68.1 v1(310.2,35.37) ; v1(348.7,39.03) 348.67,39 R56.1 R54.1 ; R45.2 v1(362.07,3.7) ; R34.1 v1(310.2,31.18) ; R41.1 v1(360.67,3.72) ; R30.1 v1(340.85,43.66) ; R55.1 v1(340.75,46.54) ; R62.1 v1(310.2,40.96) ; R48.1 v1(345.68,43.41) ; R69.1 v1(310.2,39.56)
  vias: v1(370.11,5.14) v1(371.25,5.14) v1(372.45,5.17)
P5V_USB_B1: length 4.4
  BOTTOM w0.381: U2.1 4.39,19.91 ; U2.1 2.84,19.91 ; U2.1 4.39,18.37 ; U2.1 2.84,18.37
P5V_USB_B2: length 4.4
  BOTTOM w0.381: U3.1 221.63,8.12 ; U3.1 220.08,9.66 ; U3.1 221.63,9.66 ; U3.1 220.08,8.12
P12V: length 52.2
  TOP w0.305: C4.1 v1(86.61,27.55) ; C1.1 v1(88.01,27.34) ; C13.1 v1(308.64,27.44) ; C15.1 v1(307.24,27.57)
  TOP w0.381: v1(291.65,17.61) 291.6,17.67 C16.1 ; v1(285.3,17.61) 285.34,17.65 C14.1
  LYR4 w0.381: 222.02,29.89 J27.1 ; J27.1 222.02,27.9 ; J27.1 224.02,27.9 ; J27.1 224.02,29.89 ; 216.52,27.9 J27.3 ; J27.3 216.52,29.89 ; J27.3 218.52,27.9 ; J27.3 218.52,29.89
  LYR5 w0.381: 222.02,27.9 J27.1 ; J27.1 222.02,29.89 ; J27.1 224.02,29.89 ; J27.1 224.02,27.9 ; J27.3 218.52,27.9 ; J27.3 218.52,29.89 ; J27.3 216.52,27.9 ; J27.3 216.52,29.89
  LYR6 w0.381: J27.3 218.52,27.9 ; J27.3 216.52,29.89 ; J27.3 218.52,29.89 ; J27.3 216.52,27.9 ; J27.1 224.02,29.89 ; J27.1 222.02,29.89 ; J27.1 224.02,27.9 ; J27.1 222.02,27.9
  BOTTOM w0.381: J27.3 218.52,27.9 ; J27.3 216.52,29.89 ; J27.3 218.52,29.89 ; J27.3 216.52,27.9 ; 221.7,30.21 J27.1 ; J27.1 224.34,30.21 ; J27.1 224.34,27.57 ; J27.1 221.7,27.57
  vias: v1(12.25,43.01) v1(12.25,41.74) v1(12.25,40.47) v1(13.52,43.01) v1(13.52,41.74) v1(13.52,40.47) v1(14.79,43.01) v1(14.79,41.74) v1(14.79,40.47) v1(16.06,43.01) v1(16.06,41.74) v1(16.06,40.47) v1(17.33,43.01) v1(17.33,41.74) v1(17.33,40.47) v1(18.6,43.01) v1(18.6,41.74) v1(18.6,40.47) v1(18.6,39.2) v1(18.6,37.93) v1(19.87,43.01) v1(19.87,41.74) v1(19.87,40.47) v1(19.87,39.2) v1(19.87,37.93) v1(21.14,43.01) v1(21.14,41.74) v1(21.14,40.47) v1(21.14,39.2) v1(21.14,37.93) v1(22.41,43.01) v1(22.41,41.74) v1(22.41,40.47) v1(22.41,39.2) v1(22.41,37.93) v1(23.68,43.01) v1(23.68,41.74) v1(23.68,40.47) v1(23.68,39.2) v1(23.68,37.93) v1(24.95,43.01) v1(24.95,41.74) v1(24.95,40.47) v1(24.95,39.2) v1(24.95,37.93) v1(26.22,43.01) v1(26.22,41.74) v1(26.22,40.47) v1(26.22,39.2) v1(26.22,37.93) v1(27.49,43.01) v1(27.49,41.74) v1(27.49,40.47) v1(27.49,39.2) v1(27.49,37.93) v1(28.76,43.01) v1(28.76,41.74) v1(28.76,40.47) v1(28.76,39.2) v1(28.76,37.93) v1(30.03,43.01) v1(30.03,41.74) v1(30.03,40.47) v1(30.03,39.2) v1(30.03,37.93) v1(31.3,41.74) v1(31.3,40.47) v1(31.3,39.2) v1(31.3,37.93) v1(32.57,41.74) v1(32.57,40.47) v1(32.57,39.2) v1(32.57,37.93) v1(54.16,24.6) v1(54.16,18.25) v1(54.16,11.9) v1(54.16,5.55) v1(55.81,26.12) v1(57.34,8.72) v1(58,41.01) v1(58,39.74) v1(58,38.47) v1(58,37.2) v1(58.73,45.43) v1(59.9,41.01) v1(59.9,39.74) v1(59.9,38.47) v1(59.9,37.2) v1(60.51,34.12) v1(60.51,27.77) v1(60.51,5.55) v1(60.64,24.6) v1(61.81,41.01) v1(61.81,39.74) v1(61.81,38.47) v1(61.81,37.2) v1(63.69,30.95) v1(63.69,8.72) v1(63.71,41.01) v1(63.71,39.74) v1(63.71,38.47) v1(63.71,37.2) v1(63.81,27.9) v1(64.96,53.68) v1(65.08,45.43) v1(65.62,41.01) v1(65.62,39.74) v1(65.62,38.47) v1(65.62,37.2) v1(66.73,27.9) v1(66.86,34.12) v1(66.86,18.25) v1(66.86,11.9) v1(66.86,5.55) v1(67.52,41.01) v1(67.52,39.74) v1(67.52,38.47) v1(67.52,37.2) v1(68.13,47.97) v1(69.15,25.49) v1(69.43,41.01) v1(69.43,39.74) v1(69.43,38.47) v1(69.43,37.2) v1(70.04,30.95) v1(70.04,21.42) v1(70.04,15.07) v1(70.04,8.72) v1(71.31,53.68) v1(71.31,49.87) v1(71.31,45.43) v1(71.33,41.01) v1(71.33,39.74) v1(71.33,38.47) v1(71.33,37.2) v1(73.21,34.12) v1(74.48,51.78) v1(74.48,47.97) v1(76.39,30.95) v1(77.66,53.68) v1(77.66,49.87) v1(79.56,34.12) v1(80.83,51.78) v1(80.83,47.97) v1(83.27,40.45) v1(83.27,30.95) v1(84.01,53.68) v1(84.01,49.87) v1(87.18,51.78) v1(90.36,53.68) v1(93.91,29.68) v1(96.71,53.68) v1(103.06,53.68) v1(103.06,44.92) v1(103.06,38.57) v1(109.41,53.68) v1(109.41,44.92) v1(115.76,53.68) v1(117.79,49.24) v1(122.11,53.68) v1(128.46,53.68) v1(129.98,46.19) v1(133.54,46.19) v1(134.81,53.68) v1(136.46,49.36) v1(140.14,46.19) v1(141.16,53.68) v1(143.06,49.36) v1(147.51,53.68) v1(150.68,53.68) v1(157.03,53.68) v1(163.38,53.68) v1(169.1,48.09) v1(169.73,53.68) v1(176.08,53.68) v1(176.08,48.09) v1(182.43,53.68) v1(182.43,48.09) v1(188.15,48.09) v1(188.15,35.39) v1(188.15,29.04) v1(188.15,22.69) v1(188.15,16.34) v1(188.15,9.49) v1(188.27,53.68) v1(191.32,51.27) v1(191.32,44.92) v1(191.32,38.57) v1(191.32,32.22) v1(191.32,25.87) v1(191.32,6.82) v1(194.5,53.68) v1(194.5,48.09) v1(194.5,35.39) v1(194.5,29.04) v1(194.5,22.69) v1(194.5,16.34) v1(194.5,9.49) v1(197.67,51.27) v1(197.67,44.92) v1(197.67,38.57) v1(197.67,32.22) v1(197.67,25.87) v1(197.67,6.82) v1(200.85,53.68) v1(200.85,48.09) v1(200.85,35.39) v1(200.85,29.04) v1(200.85,22.69) v1(200.85,16.34) v1(200.85,9.49) v1(204.02,51.27) v1(204.02,44.92) v1(204.02,38.57) v1(204.02,32.22) v1(204.02,25.87) v1(204.02,6.82) v1(207.07,53.68) v1(207.2,48.09) v1(207.2,35.39) v1(207.2,29.04) v1(207.2,22.69) v1(207.2,16.34) v1(207.2,9.49) v1(210.37,44.92) v1(210.37,38.57) v1(210.37,32.22) v1(210.37,25.87) v1(210.37,19.52) v1(213.55,53.68) v1(213.55,48.09) v1(213.55,35.39) v1(213.55,29.04) v1(213.55,22.69) v1(213.55,16.34) v1(213.55,9.49) v1(216.72,51.27) v1(216.72,44.92) v1(219.9,53.68) v1(219.9,48.09) v1(223.07,51.27) v1(223.07,44.92) v1(226.25,53.68) v1(226.25,48.09) v1(226.25,35.39) v1(226.25,29.04) v1(226.25,22.69) v1(226.25,16.34) v1(229.42,51.27) v1(229.42,44.92) v1(229.42,38.57) v1(229.42,32.22) v1(229.42,25.87) v1(229.42,19.52) v1(229.42,13.17) v1(232.6,53.68) v1(232.6,48.09) v1(232.6,35.39) v1(235.77,51.27) v1(235.77,44.92) v1(235.77,38.57) v1(238.95,53.68) v1(238.95,48.09) v1(238.95,35.39) v1(242.12,51.27) v1(242.12,44.92) v1(242.12,38.57) v1(245.3,53.68) v1(245.3,48.09) v1(248.47,51.27) v1(248.47,44.92) v1(248.47,38.57) v1(251.65,53.68) v1(251.65,48.09) v1(255.96,43.52) v1(258.63,53.68) v1(259.27,46.82) v1(259.27,43.52) v1(259.27,40.47) v1(262.44,40.47) v1(266,43.52) v1(269.43,50) v1(269.43,43.65) v1(272.6,53.17) v1(272.6,46.82) v1(272.6,40.47) v1(275.78,50) v1(275.78,43.65) v1(275.78,33.49) v1(275.78,20.79) v1(275.78,14.44) v1(275.78,8.09) v1(278.95,53.17) v1(278.95,46.82) v1(278.95,40.47) v1(278.95,11.26) v1(278.95,4.91) v1(282.13,50) v1(282.13,43.65) v1(282.13,33.49) v1(282.13,14.44) v1(282.13,8.09) v1(285.3,53.17) v1(285.3,46.82) v1(285.3,40.47) v1(285.3,30.31) v1(285.3,23.96) v1(285.3,11.26) v1(285.3,4.91) v1(288.48,50) v1(288.48,43.65) v1(288.48,33.49) v1(288.48,27.14) v1(288.48,20.79) v1(288.48,14.44) v1(288.48,8.09) v1(291.65,53.17) v1(291.65,46.82) v1(291.65,40.47) v1(291.65,30.31) v1(291.65,23.96) v1(291.65,11.26) v1(291.65,4.91) v1(294.83,50) v1(294.83,43.65) v1(294.83,33.49) v1(294.83,27.14) v1(298,53.17) v1(298,46.82) v1(298,40.47) v1(298,30.31) v1(298,23.96) v1(301.18,50) v1(301.18,43.65) v1(304.35,53.17) v1(304.35,40.47) v1(305.11,31.33) v1(308.41,51.65) v1(310.7,53.17) v1(312.99,51.65) v1(314.64,43.27)
P12V_MEZZ_B1: length 4.6
  TOP w0.305: J2.153 v1(42.3,31.74) ; J2.137 42.91,28.57 v1(42.22,29.25) ; J2.145 v1(42.3,30.47) ; J2.154 v1(43.57,31.74) ; J2.155 v1(44.84,31.74)
P12V_MEZZ_B2: length 4.6
  TOP w0.305: J14.145 v1(263.3,30.47) ; v1(263.3,29.27) 263.36,29.27 263.36,29.14 J14.137 ; J14.154 v1(264.57,31.74) ; J14.155 v1(265.84,31.74) ; J14.153 v1(263.3,31.74)
BLADE_B1_EN1: length 246.8
  TOP w0.102: v1(93.43,46.6) 93.43,48.15 93.33,48.25 J25.1 ; v1(92.17,27.52) 91.63,27.52 90.52,26.42 v1(90.52,25.87) ; J11.C4 167.75,8.37 167.75,16.21 166.06,17.89 160.42,17.89 v1(159.86,17.34) ; U1.S3 6.03,46.47 10.3,42.2 10.3,35.38 9.79,34.87 9.79,33.94 10.27,33.46 v1(10.57,33.46) ; J7.H2 126.42,14.39 125.51,15.3 125.51,17.77 129.24,21.5 v1(129.24,22.59)
  LYR3 w0.13: v1(54.44,30.67) 52.81,30.67 52.05,31.43 52.05,31.99 49.43,34.61 14.01,34.61 12.86,33.46 v1(10.57,33.46) ; v1(90.52,25.87) 90.52,26.09 86.8,29.81 86.8,41.39 92.01,46.6 v1(93.43,46.6)
  BOTTOM w0.102: v1(92.17,27.52) 94.57,27.52 94.73,27.67 99.98,27.67 101.73,25.92 116.57,25.92 120.36,22.13 128.78,22.13 v1(129.24,22.59) 130,23.36 130,26.33 131.55,27.88 134.12,27.88 136.35,25.64 144.03,25.64 146.34,23.33 157.54,23.33 159.82,21.04 159.82,17.38 v1(159.86,17.34) ; v1(54.44,30.67) 55.23,30.67 56.98,32.42 80.04,32.42 86.09,26.38 89.21,26.38 89.72,25.87 v1(90.52,25.87)
BLADE_B1_MATED_N<1>: length 27.8
  TOP w0.102: R12.1 v1(119.9,39.71)
  LYR3 w0.13: J7.I5 120.42,18.61 117.91,21.12 117.91,24.07 116.95,25.03 116.95,37.27 119.39,39.71 v1(119.9,39.71)
BLADE_B2_EN1: length 485.9
  TOP w0.102: v1(311.52,26.53) 311.52,26.56 312.7,27.74 v1(312.7,27.88) ; J28.1 314.18,48.25 314.64,47.79 314.64,46.37 v1(314.61,46.34) ; v1(380.86,17.34) 384.04,17.34 384.65,17.96 387,17.96 388.75,16.21 388.75,8.37 J23.C4
  LYR3 w0.13: v1(314.61,46.34) 312.45,44.18 312.45,40.7 312.76,40.4 313.39,40.4 314.36,39.43 314.36,36.72 313.48,35.85 313.29,35.85 312.45,35.01 312.45,28.13 v1(312.7,27.88) ; v1(6.03,43.01) 6.56,42.48 7.25,42.48 13.42,36.3 50.99,36.3 53.5,33.79 v1(54.46,33.79) ; J19.H2 348.19,15.11 348.19,16.8 349.69,18.3 v1(349.69,21.12)
  BOTTOM w0.102: v1(54.46,33.79) 54.52,33.74 54.97,33.74 56.12,34.89 79.48,34.89 97.31,52.72 266.96,52.72 268.03,51.65 304.27,51.65 306.5,49.43 308.45,49.43 311,46.88 311,27.05 v1(311.52,26.53) ; U1.S10 v1(6.03,43.01) ; v1(380.86,17.34) 380.88,17.36 380.88,21.15 378.44,23.58 367.37,23.58 365.01,25.95 356.52,25.95 354.31,28.16 352.2,28.16 351.26,27.22 351.26,20.79 350.88,20.41 350.4,20.41 v1(349.69,21.12) 348.42,21.12 347.35,22.19 343.07,22.19 340.74,24.52 322.31,24.52 318.98,27.85 316.27,27.85 315.91,28.21 313.55,28.21 313.22,27.88 v1(312.7,27.88)
BLADE_B2_MATED_N: length 26.9
  TOP w0.102: R40.1 v1(340.75,39.33)
  LYR3 w0.13: v1(340.75,39.33) 338.06,36.64 338.06,20.49 341.42,17.12 J19.I5
BLADE_MATED_B1_N<0>: length 42
  TOP w0.102: v1(33.84,19.44) 33.86,19.46 R85.2
  LYR4 w0.13: J1.I6 20,15.83 21.01,14.82 21.01,4.01 21.43,3.59 30.59,3.59 30.97,3.98 30.97,12.94 32.06,14.03 32.06,17.67 v1(33.84,19.44)
BLADE_MATED_B2_N<0>: length 41.7
  TOP w0.127: R86.2 v1(257.44,20.23)
  LYR4 w0.13: v1(257.44,20.23) 253.27,16.07 253.27,13.5 252.64,12.87 252.64,4.62 251.77,3.75 242.36,3.75 242.01,4.09 242.01,14.82 241,15.83 J13.I6
CLK_100M_B1_N<0>: length 57.5
  TOP w0.127: J2.138 43.72,28.08 42.28,28.08 36.24,34.12 21.84,34.12 14.84,27.13 14.84,5.76 14.67,5.59 14.55,5.59 J1.B9
CLK_100M_B1_N<1>: length 54.9
  TOP w0.127: J2.140 46.75,28.57 46.11,29.2 v1(46.11,29.2)
  LYR3 w0.127: v1(46.11,29.2) 45.62,28.71 41.19,28.71 36.88,33.02 20.81,33.02 14.87,27.08 14.87,9.92 14.74,9.79 14.55,9.79 J1.E9
CLK_100M_B1_N<2>: length 55.4
  TOP w0.127: v1(48.65,29.2) J2.142
  BOTTOM w0.127: v1(48.65,29.2) 48.17,28.72 47.18,28.72 46.91,28.99 46.91,29.61 46.52,29.99 45.71,29.99 45.31,29.59 45.31,29 45.03,28.72 41.53,28.72 36.07,34.18 22.94,34.18 15.55,26.78 15.53,26.78 14.86,26.11 14.86,26.09 14.84,26.07 14.84,14.16 14.67,13.99 14.55,13.99 J1.H9
CLK_100M_B1_N<3>: length 53.7
  TOP w0.127: J2.144 51.81,28.57 51.19,29.18 v1(51.19,29.2)
  LYR6 w0.127: v1(51.19,29.2) 50.7,28.71 49.55,28.71 49.44,28.83 49.44,29.62 49.06,29.99 44.27,29.99 42.51,28.24 40.28,28.24 35.45,33.07 20.52,33.07 14.84,27.39 14.84,18.35 14.68,18.19 14.55,18.19 J1.K9
CLK_100M_B1_P<0>: length 57.5
  TOP w0.127: J1.A9 14.55,5.29 14.8,5.29 15.15,5.63 15.15,27 21.97,33.82 36.12,33.82 42.16,27.78 43.72,27.78 J2.130
CLK_100M_B1_P<1>: length 54.9
  TOP w0.127: J2.132 46.74,27.3 46.11,27.93 v1(46.11,27.93)
  LYR3 w0.127: J1.D9 14.55,9.49 14.86,9.49 15.16,9.8 15.16,26.96 20.93,32.73 36.76,32.73 41.07,28.42 45.62,28.42 v1(46.11,27.93)
CLK_100M_B1_P<2>: length 55.4
  TOP w0.127: J2.134 49.29,27.32 48.68,27.93 v1(48.65,27.93)
  BOTTOM w0.127: J1.G9 14.55,13.69 14.8,13.69 15.15,14.03 15.15,25.95 15.16,25.96 15.16,25.99 15.65,26.48 15.68,26.48 23.07,33.87 35.95,33.87 41.4,28.42 45.16,28.42 45.62,28.87 45.62,29.46 45.84,29.69 46.4,29.69 46.6,29.48 46.6,28.87 47.06,28.41 48.17,28.41 v1(48.65,27.93)
CLK_100M_B1_P<3>: length 53.7
  TOP w0.127: v1(51.19,27.93) 51.19,27.93 J2.136
  LYR6 w0.127: J1.J9 14.55,17.89 14.8,17.89 15.13,18.22 15.13,27.27 20.64,32.78 35.33,32.78 40.16,27.95 42.64,27.95 44.39,29.7 48.94,29.7 49.14,29.5 49.14,28.7 49.43,28.42 50.7,28.42 v1(51.19,27.93)
CLK_100M_B2_N<0>: length 57.8
  TOP w0.127: J13.B9 235.55,5.59 235.67,5.59 235.84,5.76 235.84,27.13 243.22,34.51 256.86,34.51 263.28,28.08 264.72,28.08 J14.138
CLK_100M_B2_N<1>: length 56.2
  TOP w0.127: v1(267.11,29.2) J14.140
  LYR3 w0.127: v1(267.11,29.2) 266.62,28.71 262.19,28.71 256.33,34.57 243.36,34.57 235.87,27.08 235.87,9.92 235.74,9.79 235.55,9.79 J13.E9
CLK_100M_B2_N<2>: length 55.4
  TOP w0.127: v1(269.65,29.2) J14.142
  BOTTOM w0.127: J13.H9 235.55,13.99 235.67,13.99 235.84,14.16 235.84,26.07 235.86,26.09 235.86,26.11 236.53,26.78 236.55,26.78 243.94,34.18 257.07,34.18 262.53,28.72 266.03,28.72 266.31,29 266.31,29.59 266.71,29.99 267.52,29.99 267.91,29.61 267.91,28.99 268.18,28.72 269.17,28.72 v1(269.65,29.2)
CLK_100M_B2_N<3>: length 53.7
  TOP w0.127: J14.144 v1(272.19,29.2)
  LYR6 w0.127: J13.K9 235.55,18.19 235.68,18.19 235.84,18.35 235.84,27.39 241.52,33.07 256.45,33.07 261.28,28.24 263.51,28.24 265.26,29.98 270.07,29.98 270.44,29.62 270.44,28.83 270.55,28.71 271.7,28.71 v1(272.19,29.2)
CLK_100M_B2_P<0>: length 57.8
  TOP w0.127: J14.130 264.72,27.78 263.16,27.78 256.73,34.2 243.35,34.2 236.15,27 236.15,5.63 235.8,5.29 235.55,5.29 J13.A9
CLK_100M_B2_P<1>: length 56.2
  TOP w0.127: v1(267.11,27.93) J14.132
  LYR3 w0.127: v1(267.11,27.93) 266.62,28.42 262.07,28.42 256.21,34.28 243.48,34.28 236.16,26.96 236.16,9.8 235.86,9.49 235.55,9.49 J13.D9
CLK_100M_B2_P<2>: length 55.4
  TOP w0.127: v1(269.65,27.93) J14.134
  BOTTOM w0.127: v1(269.65,27.93) 269.17,28.41 268.06,28.41 267.6,28.87 267.6,29.48 267.4,29.69 266.84,29.69 266.62,29.46 266.62,28.87 266.16,28.42 262.4,28.42 256.95,33.87 244.07,33.87 236.68,26.48 236.65,26.48 236.16,25.99 236.16,25.96 236.15,25.95 236.15,14.03 235.8,13.69 235.55,13.69 J13.G9
CLK_100M_B2_P<3>: length 53.7
  TOP w0.127: J14.136 v1(272.19,27.93)
  LYR6 w0.127: J13.J9 235.55,17.89 235.8,17.89 236.13,18.22 236.13,27.27 241.64,32.78 256.33,32.78 261.16,27.95 263.64,27.95 265.38,29.69 269.95,29.69 270.14,29.5 270.14,28.7 270.43,28.42 271.7,28.42 v1(272.19,27.93)
ETH10G_B1_MOD_ABS: length 36.6
  TOP w0.102: v1(139.13,23.52) 139.11,23.51 J5.6 ; v1(123.04,48.53) R15.2 R29.1
  LYR3 w0.13: v1(123.04,48.53) 124.06,47.51 124.06,45.78 124.67,45.17 125.71,45.17 126.98,43.9 126.98,43.22 137.83,32.37 137.83,23.96 138.28,23.51 139.11,23.51 v1(139.13,23.52)
ETH10G_B1_PRES_N: length 41.5
  TOP w0.102: R15.1 v1(119.6,48.53)
  LYR3 w0.13: v1(119.6,48.53) 120.96,47.17 120.96,45.17 125.34,40.79 125.34,40.06 124.77,39.48 124.47,39.48 124.12,39.14 124.12,38.48 124.42,38.18 125.82,38.18 128.73,35.27 128.73,25.54 127.34,24.14 127.34,21.32 125.64,19.62 125.64,16.52 J7.I2
ETH10G_B1_RS0: length 27.7
  TOP w0.102: 126.96,43.21 R23.1 ; 126.96,43.21 R22.2 ; 126.96,43.21 v1(127.78,43.21) ; v1(138.31,24.15) J5.7
  LYR3 w0.13: v1(127.78,43.21) 138.31,32.68 v1(138.31,24.15)
ETH10G_B1_RS1: length 29.9
  TOP w0.102: R25.1 R24.2 122.19,44.09 v1(123.01,44.09) ; v1(136.71,24.17) J5.9
  LYR3 w0.13: v1(136.71,24.17) 136.71,25.39 131.15,30.95 131.15,34.79 126.58,39.36 126.58,40.53 v1(123.01,44.09)
ETH10G_B1_RX_LOS: length 32.3
  TOP w0.102: J5.8 137.51,23.5 v1(137.5,23.5) ; R27.2 123.29,46.92 v1(123.3,46.93)
  LYR3 w0.13: v1(137.5,23.5) 137.24,23.76 137.24,32.07 128.33,40.98 127.69,40.98 123.3,45.38 v1(123.3,46.93)
ETH10G_B1_RXN: length 14.7
  TOP w0.107: J5.12 137.11,12.54 137.29,12.36 137.29,11.04 arc(137.24,10.79) v1(137.1,10.58)
  BOTTOM w0.107: J7.E1 128.87,9.79 arc(128.91,9.77) 128.95,9.76 129.27,9.76 arc(129.61,9.69) 129.9,9.5 130.32,9.08 arc(130.4,9.02) 130.49,9 131.78,9 arc(131.85,9.03) 131.88,9.11 arc(131.95,9.25) 132.09,9.31 132.31,9.31 arc(132.46,9.25) 132.52,9.11 arc(132.55,9.03) 132.62,9 134.07,9 arc(134.14,9.03) 134.17,9.11 arc(134.22,9.23) 134.35,9.28 134.63,9.28 arc(134.75,9.23) 134.81,9.11 arc(134.83,9.03) 134.91,9 136.61,9 arc(137.09,9.21) 137.29,9.69 137.29,10.13 arc(137.24,10.37) v1(137.1,10.58)
ETH10G_B1_RXP: length 14.7
  TOP w0.107: J5.13 137.91,12.56 137.73,12.37 137.73,11.04 arc(137.78,10.79) v1(137.92,10.58)
  BOTTOM w0.107: J7.D1 128.87,9.29 arc(128.91,9.31) 128.95,9.32 129.27,9.32 arc(129.44,9.29) 129.59,9.19 130.01,8.77 arc(130.23,8.62) 130.49,8.57 136.61,8.57 arc(137.4,8.9) 137.73,9.69 137.73,10.13 arc(137.78,10.37) v1(137.92,10.58)
ETH10G_B1_SCL: length 68
  TOP w0.102: J5.5 v1(139.91,24.19) ; R28.2 v1(124.65,38.82)
  LYR3 w0.13: v1(124.65,38.82) 126.12,38.82 130.64,34.3 130.64,30.21 135.01,25.84 135.01,23.13 135.29,22.85 139.33,22.85 139.68,23.2 139.68,23.97 v1(139.91,24.19) 140.22,23.89 140.22,22.8 139.61,22.19 135.9,22.19 130.41,16.7 130.41,4.69 129.39,3.67 126.02,3.67 125.41,4.28 125.41,9.33 124.5,10.24 J7.E3
ETH10G_B1_SDA: length 74.8
  TOP w0.102: J5.4 140.71,23.52 v1(140.7,23.53) ; R26.2 125.1,37.43 125.05,37.38 v1(124.47,37.38)
  LYR3 w0.13: 124.3,8.84 J7.D3 ; 124.3,8.84 124.28,8.84 123.43,9.69 123.43,16.01 123.88,16.47 123.88,18.83 122.97,19.75 122.97,21.27 127.64,25.95 127.64,34.71 124.98,37.38 v1(124.47,37.38) ; 124.3,8.84 123.4,7.94 123.4,4.05 124.21,3.24 129.95,3.24 131.05,4.33 131.05,16.47 136.2,21.63 139.91,21.63 140.7,22.42 v1(140.7,23.53)
ETH10G_B1_TX_DIS: length 31.9
  TOP w0.102: R21.1 R20.2 v1(128.15,45.87) ; v1(141.51,24.07) J5.3
  LYR3 w0.13: v1(128.15,45.87) 128.15,43.7 130.11,41.74 130.11,41.72 139.07,32.75 139.07,26.56 141.51,24.12 v1(141.51,24.07)
ETH10G_B1_TX_FAULT: length 33.5
  TOP w0.102: v1(127.9,48.54) 126.96,48.54 R18.2 ; v1(142.31,23.53) J5.2
  LYR3 w0.13: v1(127.9,48.54) 128.84,47.6 128.84,43.78 139.58,33.03 139.58,26.78 142.31,24.05 v1(142.31,23.53)
ETH10G_B1_TXN: length 23.3
  TOP w0.107: J5.19 142.71,15.11 142.53,15.29 142.53,18.99 arc(142.31,19.51) 141.8,19.72 141.31,19.72 arc(141.06,19.77) v1(140.85,19.91)
  BOTTOM w0.107: J7.H1 128.87,13.99 arc(128.91,13.97) 128.95,13.96 129.22,13.96 arc(129.4,13.99) 129.56,14.1 130.45,14.99 arc(130.83,15.56) 130.97,16.24 arc(131.99,18.7) 134.45,19.72 140.39,19.72 arc(140.64,19.77) v1(140.85,19.91)
ETH10G_B1_TXP: length 23.3
  TOP w0.107: J5.18 141.91,15.12 142.09,15.3 142.09,18.99 arc(142.01,19.2) 141.8,19.29 141.31,19.29 arc(141.06,19.24) v1(140.85,19.1)
  BOTTOM w0.107: J7.G1 128.87,13.49 arc(128.91,13.51) 128.95,13.52 129.22,13.52 arc(129.57,13.59) 129.87,13.79 130.76,14.68 arc(131.24,15.4) 131.4,16.24 arc(132.3,18.4) 134.45,19.29 136.82,19.29 arc(136.92,19.25) 136.96,19.14 136.96,19.14 arc(137.01,19.03) 137.12,18.99 137.45,18.99 arc(137.55,19.03) 137.6,19.14 137.6,19.16 arc(137.64,19.25) 137.73,19.29 139,19.29 arc(139.09,19.25) 139.12,19.16 139.12,19.14 arc(139.16,19.05) 139.26,19.01 139.63,19.01 arc(139.72,19.05) 139.76,19.14 arc(139.79,19.24) 139.89,19.29 140.4,19.29 arc(140.64,19.24) v1(140.85,19.1)
ETH10G_B2_MOD_ABS: length 36.5
  TOP w0.102: v1(344.02,48.12) 344,48.15 R43.2 343.02,49.62 ; v1(360.13,23.52) 360.11,23.51 J17.6
  LYR3 w0.13: v1(344.02,48.12) 344.1,48.04 345.27,48.04 347.81,45.5 347.81,43.14 348.42,42.53 349.36,42.53 358.6,33.29 358.6,26.9 358.62,26.89 358.63,26.89 360.13,25.39 v1(360.13,23.52)
ETH10G_B2_PRES_N: length 39.8
  TOP w0.102: R43.1 v1(340.72,48.15)
  LYR3 w0.13: v1(340.72,48.15) 342.42,46.44 342.45,46.44 344.91,43.98 344.91,38.72 345.17,38.47 346.21,38.47 350.27,34.4 350.27,25.95 348.75,24.42 348.75,19.72 346.62,17.59 346.62,16.54 J19.I2
ETH10G_B2_RS0: length 26.6
  TOP w0.102: v1(359.31,24.15) J17.7 ; R50.2 R51.1 v1(348.93,41.74)
  LYR3 w0.13: v1(359.31,24.15) 359.31,25.34 358.22,26.43 358.22,32.45 v1(348.93,41.74)
ETH10G_B2_RS1: length 31.4
  TOP w0.102: v1(345.63,46.14) 345.64,46.13 R53.1 R52.2 ; v1(357.71,24.17) J17.9
  LYR3 w0.13: v1(345.63,46.14) 346.64,45.12 346.64,41.92 351.39,37.17 351.39,30.56 357.71,24.24 v1(357.71,24.17)
ETH10G_B2_RX_LOS: length 33.1
  TOP w0.102: J17.8 358.51,23.5 v1(358.5,23.5) ; v1(344.25,46.54) R55.2
  LYR3 w0.13: v1(344.25,46.54) 344.67,46.95 345.78,46.95 347.2,45.53 347.2,42.02 351.72,37.5 351.72,31 358.5,24.21 v1(358.5,23.5)
ETH10G_B2_RXN: length 14.7
  TOP w0.107: J17.12 358.11,12.54 358.29,12.36 358.29,11.04 arc(358.24,10.79) v1(358.1,10.58)
  BOTTOM w0.107: J19.E1 349.87,9.79 arc(349.91,9.77) 349.95,9.76 350.27,9.76 arc(350.61,9.69) 350.9,9.5 351.32,9.08 arc(351.4,9.02) 351.49,9 352.78,9 arc(352.85,9.03) 352.88,9.11 arc(352.95,9.25) 353.09,9.31 353.31,9.31 arc(353.46,9.25) 353.52,9.11 arc(353.55,9.03) 353.62,9 355.07,9 arc(355.14,9.03) 355.17,9.11 arc(355.22,9.23) 355.35,9.28 355.63,9.28 arc(355.75,9.23) 355.81,9.11 arc(355.83,9.03) 355.91,9 357.61,9 arc(358.09,9.21) 358.29,9.69 358.29,10.13 arc(358.24,10.37) v1(358.1,10.58)
ETH10G_B2_RXP: length 14.7
  TOP w0.107: J17.13 358.91,12.56 358.73,12.37 358.73,11.04 arc(358.78,10.79) v1(358.92,10.58)
  BOTTOM w0.107: J19.D1 349.87,9.29 arc(349.91,9.31) 349.95,9.32 350.27,9.32 arc(350.44,9.29) 350.59,9.19 351.01,8.77 arc(351.23,8.62) 351.49,8.57 357.61,8.57 arc(358.4,8.9) 358.73,9.69 358.73,10.13 arc(358.78,10.37) v1(358.92,10.58)
ETH10G_B2_SCL: length 84
  TOP w0.102: J17.5 v1(360.91,24.19) ; R56.2 v1(345.45,39)
  LYR3 w0.13: v1(360.91,24.19) 360.91,22.77 360.61,22.47 358.58,22.47 356.52,24.52 356.52,24.88 350.68,30.72 350.68,34.7 346.37,39 v1(345.45,39)
  LYR6 w0.13: v1(352.76,4.74) 352.76,12.37 352.16,12.98 352.16,16.6 355.99,20.43 355.99,27.5 351.95,31.53 351.95,32.8 345.75,39 v1(345.45,39)
  BOTTOM w0.102: v1(352.76,4.74) 352.76,4.76 352.31,5.22 351.64,5.22 350.09,3.66 347.11,3.66 346.56,4.2 346.56,9.1 J19.E3
ETH10G_B2_SDA: length 79.4
  TOP w0.102: R54.2 v1(345.45,37.6) ; J17.4 361.71,23.52 v1(361.7,23.53)
  LYR3 w0.13: v1(361.7,23.53) 361.7,21.91 360.22,20.43 355.18,20.43 351.82,17.08 v1(351.82,4.74)
  LYR6 w0.13: v1(345.45,37.6) 346.35,37.6 351.23,32.72 351.23,31.64 355.35,27.52 355.35,20.4 351.82,16.87 351.82,12.72 352.39,12.16 352.39,6.1 arc(352.24,5.36) v1(351.82,4.74)
  BOTTOM w0.102: J19.D3 346.26,8 346.26,4.08 346.93,3.4 350.9,3.4 351.82,4.33 v1(351.82,4.74)
ETH10G_B2_TX_DIS: length 29.9
  TOP w0.102: R49.1 R48.2 348.58,43.41 v1(348.6,43.4) ; v1(362.51,24.07) J17.3
  LYR3 w0.13: v1(362.51,24.07) 362.51,24.12 359.11,27.52 359.11,34.02 349.74,43.4 v1(348.6,43.4)
ETH10G_B2_TX_FAULT: length 33.8
  TOP w0.102: v1(348.72,48.88) 348.71,48.87 R46.2 ; v1(363.31,23.53) J17.2
  LYR3 w0.13: v1(363.31,23.53) 363.31,24.05 359.75,27.62 359.75,34.48 350.5,43.73 350.5,47.11 v1(348.72,48.88)
ETH10G_B2_TXN: length 23.3
  TOP w0.107: J17.19 363.71,15.11 363.53,15.29 363.53,18.99 arc(363.31,19.51) 362.8,19.72 362.31,19.72 arc(362.06,19.77) v1(361.85,19.91)
  BOTTOM w0.107: J19.H1 349.87,13.99 arc(349.91,13.97) 349.95,13.96 350.22,13.96 arc(350.4,13.99) 350.56,14.1 351.45,14.99 arc(351.83,15.56) 351.97,16.24 arc(352.99,18.7) 355.45,19.72 361.39,19.72 arc(361.64,19.77) v1(361.85,19.91)
ETH10G_B2_TXP: length 23.3
  TOP w0.107: J17.18 362.91,15.12 363.09,15.3 363.09,18.99 arc(363.01,19.2) 362.8,19.29 362.31,19.29 arc(362.06,19.24) v1(361.85,19.1)
  BOTTOM w0.107: J19.G1 349.87,13.49 arc(349.91,13.51) 349.95,13.52 350.22,13.52 arc(350.57,13.59) 350.87,13.79 351.76,14.68 arc(352.24,15.4) 352.4,16.24 arc(353.3,18.4) 355.45,19.29 357.82,19.29 arc(357.92,19.25) 357.96,19.14 357.96,19.14 arc(358.01,19.03) 358.12,18.99 358.45,18.99 arc(358.55,19.03) 358.6,19.14 358.6,19.16 arc(358.64,19.25) 358.73,19.29 360,19.29 arc(360.09,19.25) 360.12,19.16 360.12,19.14 arc(360.16,19.05) 360.26,19.01 360.63,19.01 arc(360.72,19.05) 360.76,19.14 arc(360.79,19.24) 360.89,19.29 361.4,19.29 arc(361.64,19.24) v1(361.85,19.1)
ETH40G_B1_INT_N: length 60.1
  TOP w0.102: v1(92.59,40.93) R78.2 ; v1(105.47,4.81) 105.61,4.94 J8.28
  LYR3 w0.13: v1(98.14,4.78) 97.29,4.78 97.26,4.82 95.94,4.82 95.5,5.26 95.5,24.41 94.55,25.36 92.39,25.36 88.32,29.43 88.32,39.26 89.31,40.25 91.9,40.25 v1(92.59,40.93)
  LYR6 w0.13: v1(105.47,4.81) 105.23,5.05 105.23,7.02 104.83,7.41 99.05,7.41 98.14,6.5 v1(98.14,4.78)
ETH40G_B1_LPMODE: length 64.6
  TOP w0.102: R79.1 v1(89.42,42.33) ; R84.2 v1(87.76,34.71) ; v1(108.01,4.32) J8.31
  LYR3 w0.13: v1(97.48,4.13) 96.12,4.13 95.21,5.04 95.21,24.19 94.42,24.98 92.26,24.98 87.28,29.96 87.28,34.23 v1(87.76,34.71) 87.76,41.26 88.83,42.33 v1(89.42,42.33)
  BOTTOM w0.102: v1(108.01,4.32) 107.97,4.36 107.97,4.91 107.62,5.26 103.2,5.26 102.6,4.66 102.6,2.56 102.05,2.01 99.04,2.01 98.12,2.94 98.12,3.82 97.81,4.13 v1(97.48,4.13)
ETH40G_B1_MODPRS_N: length 67.2
  TOP w0.102: R80.1 v1(119.95,38.19) ; J8.27 v1(104.81,4.3)
  LYR3 w0.13: v1(117,5.22) 117.3,4.93 117.3,4.46 117.96,3.79 118.91,3.79 119.21,4.09 119.21,17.83 118.19,18.86 116.42,18.86 114.28,20.99 114.28,31.18 114.59,31.48 114.59,31.53 116.09,33.03 116.09,37.83 118.83,40.58 120.15,40.58 120.71,40.02 120.71,38.93 119.97,38.19 v1(119.95,38.19)
  LYR4 w0.13: v1(117,5.22) 116.26,5.22 112.74,1.7 107.68,1.7 107.35,2.02 107.35,3.42 106.87,3.9 105.21,3.9 v1(104.81,4.3)
ETH40G_B1_MODSEL_N: length 37.3
  TOP w0.102: v1(108.44,14.34) 108.44,10.96 107.61,10.13 J8.8 ; v1(92.57,36.74) R76.2 R77.1
  LYR3 w0.13: v1(92.57,36.74) 99.09,30.22 99.09,26.78 107.14,18.72 107.14,15.63 v1(108.44,14.34)
ETH40G_B1_PRES_N: length 29.6
  TOP w0.102: R80.2 122.97,38.19 v1(123.02,38.14)
  LYR3 w0.13: v1(123.02,38.14) 122.51,37.63 120.73,37.63 117.71,34.61 117.71,25.54 119.31,23.94 119.31,20.87 121.17,19.01 121.17,15.28 120.42,14.53 J7.H5
ETH40G_B1_RESET_N: length 45.1
  TOP w0.102: J8.9 106.81,11.41 106.37,11.85 v1(105.25,11.85) ; R75.2 v1(89.58,32.55) ; R83.2 v1(92.77,39.54)
  LYR3 w0.13: v1(92.77,39.54) 90.99,37.76 90.99,33.87 89.67,32.55 v1(89.58,32.55) 88.86,31.83 88.86,30.42 90.08,29.2 90.08,28.56 92.72,25.92 94.77,25.92 96.41,24.29 98.47,24.29 104.1,18.66 104.1,12.78 105.03,11.85 v1(105.25,11.85)
ETH40G_B1_RX0N: length 36.2
  TOP w0.107: J8.18 99.61,9.64 arc(99.62,9.68) 99.64,9.72 99.76,9.84 arc(99.78,9.87) 99.79,9.91 99.79,10.99 arc(99.74,11.24) v1(99.6,11.45)
  BOTTOM w0.107: J7.F6 118.87,11.09 arc(118.91,11.07) 118.95,11.06 119.05,11.06 arc(119.15,11.1) 119.19,11.19 119.19,17.17 arc(119.12,17.52) 118.92,17.82 arc(118.45,18.02) 117.97,17.82 arc(117.32,17.39) 116.56,17.23 114.45,17.23 arc(113.87,17.12) 113.37,16.79 113.21,16.62 113.21,16.33 112.92,16.04 112.62,16.04 112.33,15.75 112.33,15.46 112.04,15.17 111.75,15.17 111.46,14.88 111.46,14.58 111.17,14.29 110.88,14.29 110.58,14 110.58,13.71 110.29,13.42 110,13.42 107.46,10.88 arc(104.89,9.16) 101.86,8.56 101.24,8.56 arc(100.22,8.98) 99.79,10.01 99.79,10.99 arc(99.74,11.24) v1(99.6,11.45)
ETH40G_B1_RX0P: length 36.2
  TOP w0.107: J8.17 100.41,9.64 arc(100.4,9.68) 100.38,9.72 100.26,9.84 arc(100.24,9.87) 100.23,9.91 100.23,10.99 arc(100.28,11.24) v1(100.42,11.45)
  BOTTOM w0.107: J7.E6 118.87,10.59 arc(118.91,10.61) 118.95,10.62 119.05,10.62 arc(119.46,10.79) 119.62,11.19 119.62,17.17 arc(119.52,17.69) 119.23,18.13 arc(118.45,18.45) 117.66,18.13 arc(117.16,17.79) 116.56,17.67 114.45,17.67 arc(113.7,17.52) 113.07,17.1 107.15,11.19 arc(104.73,9.56) 101.86,8.99 101.24,8.99 arc(100.52,9.29) 100.23,10.01 100.23,10.99 arc(100.28,11.24) v1(100.42,11.45)
